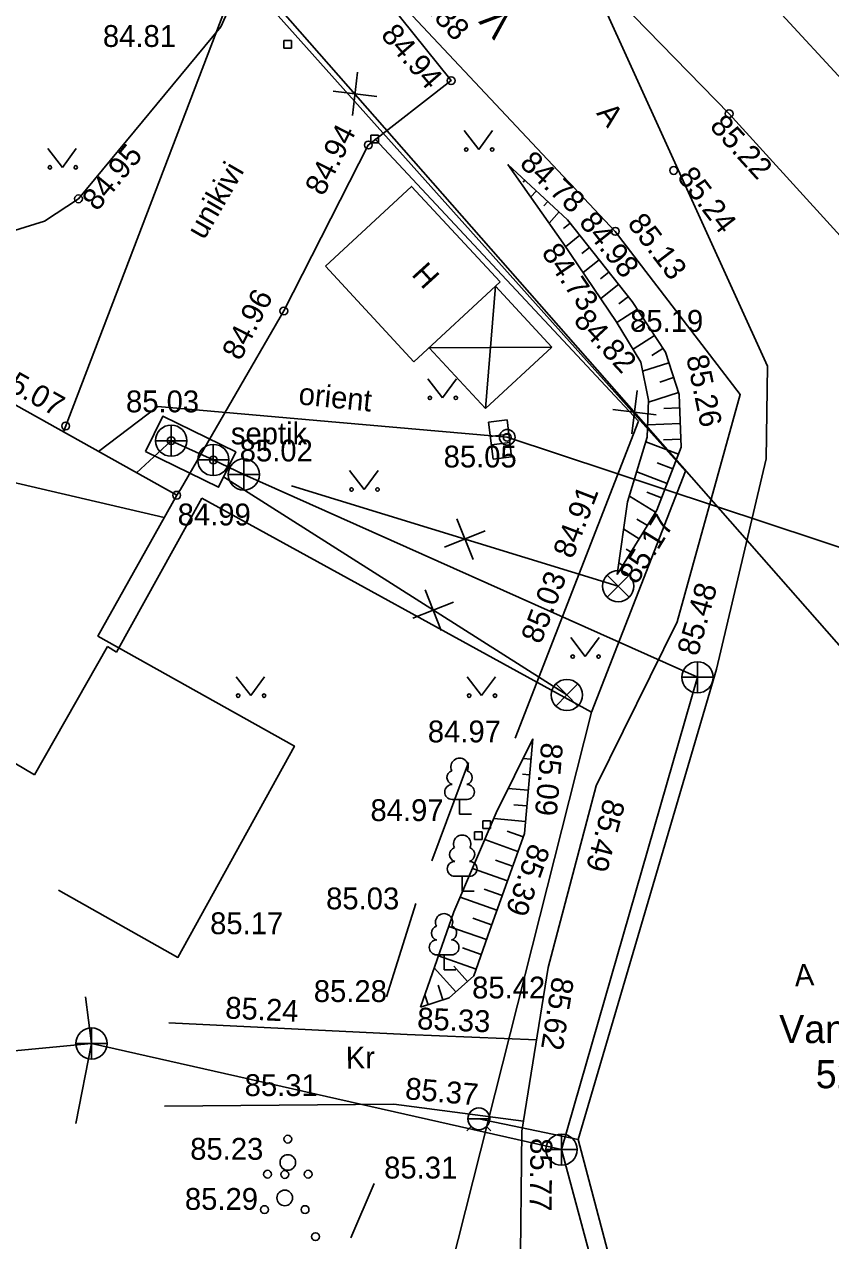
# Model space of a CAD drawing. Extents: x 648748 to 649126, y 6457789 to 6458252.
# Drawn here: x 648933.59 to 648959.42, y 6458153.11 to 6458192.08 of the extents above; entities that cross this region are included whole.
import ezdxf

# ---------------------------------------------------------------- set-up
doc = ezdxf.new("R2010")
doc.units = 0
for name, color, linetype in [('AED', 7, 'Continuous'), ('ELRAJATISMP', 7, 'Continuous'), ('HALJASTUS', 7, 'Continuous'), ('HOONE', 7, 'Continuous'), ('KKAEV', 7, 'Continuous'), ('KORGUS-EH2000', 7, 'Continuous'), ('KTRASS', 7, 'Continuous'), ('MPKAABEL', 7, 'Continuous'), ('MPOHULIIN', 7, 'Continuous'), ('PIIR', 7, 'Continuous'), ('POST', 7, 'Continuous'), ('PUU', 7, 'Continuous'), ('RAJATIS', 7, 'Continuous'), ('RAJATISEDET', 7, 'Continuous'), ('RELJEEF', 7, 'Continuous'), ('SIOHULIIN', 7, 'Continuous'), ('TEE', 7, 'Continuous'), ('TORUMP', 7, 'Continuous'), ('VKAEV', 7, 'Continuous'), ('VTRASS', 7, 'Continuous')]:
    doc.layers.add(name, color=color, linetype=linetype)

msp = doc.modelspace()

# ---------------------------------------------------------------- linework, layer by layer
at = {"layer": 'AED'}
for p, q in [((648941.902, 6458191.565), (648941.902, 6458191.315)), ((648941.902, 6458191.565), (648942.152, 6458191.565)), ((648941.902, 6458191.315), (648942.152, 6458191.315)), ((648942.152, 6458191.565), (648942.152, 6458191.315)), ((648944.692, 6458188.536), (648944.692, 6458188.286)), ((648944.692, 6458188.536), (648944.942, 6458188.536)), ((648944.692, 6458188.286), (648944.942, 6458188.286)), ((648953.264, 6458179.371), (648944.817, 6458188.411)), ((648944.942, 6458188.536), (648944.942, 6458188.286)), ((648949.319, 6458169.205), (648953.264, 6458179.371)), ((648948.279, 6458166.562), (648948.279, 6458166.312)), ((648948.279, 6458166.562), (648948.529, 6458166.562)), ((648948.529, 6458166.562), (648948.529, 6458166.312)), ((648948.01, 6458166.211), (648948.01, 6458165.961)), ((648948.01, 6458166.211), (648948.26, 6458166.211)), ((648948.01, 6458165.961), (648948.26, 6458165.961)), ((648948.26, 6458166.211), (648948.26, 6458165.961)), ((648948.279, 6458166.312), (648948.529, 6458166.312)), ((648944.05, 6458153.204), (648944.797, 6458154.938))]:
    msp.add_line(p, q, dxfattribs=at)
at = {"layer": 'ELRAJATISMP'}
for p, q in [((648949.056, 6458179.411), (648948.464, 6458179.337)), ((648948.464, 6458179.337), (648948.611, 6458178.151)), ((648949.203, 6458178.225), (648949.056, 6458179.411)), ((648949.113, 6458178.952), (648948.521, 6458178.879)), ((648949.147, 6458178.683), (648948.554, 6458178.61)), ((648948.611, 6458178.151), (648949.203, 6458178.225))]:
    msp.add_line(p, q, dxfattribs=at)
at = {"layer": 'HALJASTUS'}
for p, q in [((648947.687, 6458188.675), (648948.151, 6458188.069)), ((648948.151, 6458188.069), (648948.596, 6458188.675)), ((648934.349, 6458188.105), (648934.813, 6458187.499)), ((648934.813, 6458187.499), (648935.258, 6458188.105)), ((648946.524, 6458180.718), (648946.987, 6458180.111)), ((648946.987, 6458180.111), (648947.433, 6458180.718)), ((648944.015, 6458177.784), (648944.478, 6458177.177)), ((648944.478, 6458177.177), (648944.924, 6458177.784)), ((648951.098, 6458172.431), (648951.561, 6458171.824)), ((648951.561, 6458171.824), (648952.007, 6458172.431)), ((648940.381, 6458171.178), (648940.845, 6458170.572)), ((648940.845, 6458170.572), (648941.29, 6458171.178)), ((648947.78, 6458171.178), (648948.244, 6458170.572)), ((648948.244, 6458170.572), (648948.689, 6458171.178)), ((648947.821, 6458168.433), (648946.644, 6458165.284)), ((648946.134, 6458163.91), (648945.194, 6458160.922))]:
    msp.add_line(p, q, dxfattribs=at)
for centre in [(648947.75, 6458188.069), (648948.579, 6458188.069), (648934.412, 6458187.499), (648935.241, 6458187.499), (648946.586, 6458180.111), (648947.415, 6458180.111), (648944.077, 6458177.177), (648944.906, 6458177.177), (648951.16, 6458171.824), (648951.989, 6458171.824), (648940.444, 6458170.572), (648941.273, 6458170.572), (648947.843, 6458170.572), (648948.672, 6458170.572)]:
    msp.add_circle(centre, 0.055, dxfattribs=at)
at = {"layer": 'HOONE'}
msp.add_lwpolyline([(648931.219, 6458160.37), (648921.451, 6458165.798), (648930.234, 6458181.603), (648938.475, 6458176.993), (648935.95, 6458172.478), (648942.245, 6458168.957), (648938.513, 6458162.187), (648934.684, 6458164.338)], dxfattribs=at)
at = {"layer": 'KKAEV'}
for p, q in [((648938.299, 6458178.241), (648938.299, 6458179.241)), ((648937.799, 6458178.741), (648938.799, 6458178.741)), ((648939.648, 6458177.623), (648939.648, 6458178.623)), ((648939.148, 6458178.123), (648940.148, 6458178.123)), ((648940.622, 6458177.156), (648940.622, 6458178.156)), ((648940.122, 6458177.656), (648941.122, 6458177.656)), ((648955.157, 6458170.66), (648955.157, 6458171.66)), ((648954.657, 6458171.16), (648955.657, 6458171.16)), ((648935.747, 6458158.927), (648935.747, 6458159.927)), ((648935.247, 6458159.427), (648936.247, 6458159.427)), ((648950.799, 6458155.525), (648950.799, 6458156.525)), ((648950.299, 6458156.025), (648951.299, 6458156.025))]:
    msp.add_line(p, q, dxfattribs=at)
msp.add_lwpolyline([(648937.477, 6458178.39), (648938.029, 6458179.522), (648940.368, 6458178.382), (648939.816, 6458177.25), (648937.477, 6458178.39)], dxfattribs=at)
for centre in [(648938.299, 6458178.741), (648939.648, 6458178.123), (648940.622, 6458177.656), (648955.157, 6458171.16), (648935.747, 6458159.427), (648950.799, 6458156.025)]:
    msp.add_circle(centre, 0.5, dxfattribs=at)
at = {"layer": 'KORGUS-EH2000'}
for centre in [(648947.267, 6458190.279), (648956.171, 6458189.218), (648944.613, 6458188.214), (648954.397, 6458187.4), (648935.329, 6458186.492), (648952.525, 6458185.448), (648941.907, 6458182.899), (648934.917, 6458179.213), (648938.299, 6458178.741), (648949.064, 6458178.85), (648939.648, 6458178.123), (648938.475, 6458176.993)]:
    msp.add_circle(centre, 0.125, dxfattribs=at)
at = {"layer": 'KTRASS'}
for p, q in [((648938.299, 6458178.741), (648937.191, 6458177.711)), ((648938.299, 6458178.741), (648939.648, 6458178.123)), ((648940.622, 6458177.656), (648939.648, 6458178.123)), ((648955.157, 6458171.16), (648940.622, 6458177.656)), ((648950.975, 6458170.593), (648939.976, 6458177.578)), ((648942.155, 6458177.295), (648952.619, 6458174.082)), ((648947.45, 6458176.24), (648947.967, 6458174.939)), ((648947.058, 6458175.331), (648948.359, 6458175.848)), ((648946.434, 6458173.963), (648946.951, 6458172.662)), ((648946.042, 6458173.054), (648947.343, 6458173.572)), ((648950.799, 6458156.025), (648955.157, 6458171.16)), ((648935.747, 6458159.427), (648935.548, 6458160.919)), ((648935.747, 6458159.427), (648918.483, 6458157.779)), ((648935.747, 6458159.427), (648935.238, 6458156.861)), ((648950.799, 6458156.025), (648935.747, 6458159.427)), ((648957.262, 6458132.173), (648950.799, 6458156.025))]:
    msp.add_line(p, q, dxfattribs=at)
at = {"layer": 'MPKAABEL'}
msp.add_lwpolyline([(648935.967, 6458178.396), (648937.865, 6458179.832), (648943.331, 6458179.353), (648949.064, 6458178.85)], dxfattribs=at)
at = {"layer": 'MPOHULIIN'}
msp.add_lwpolyline([(648949.064, 6458178.85), (648980.689, 6458168.372), (648993.115, 6458162.488), (649016.276, 6458164.81), (649054.033, 6458170.656), (649094.361, 6458177.194), (649107.677, 6458175.236)], dxfattribs=at)
at = {"layer": 'PIIR'}
for p, q in [((648954.77, 6458177.77), (648938.76, 6458195.67)), ((648955.09, 6458195.42), (648987.99, 6458159.58)), ((648951.76, 6458170.04), (648954.77, 6458177.77)), ((648936.55, 6458171.97), (648939.28, 6458176.9)), ((648939.28, 6458176.9), (648951.76, 6458170.04)), ((648933.92, 6458168.04), (648936.26, 6458172.15)), ((648936.26, 6458172.15), (648936.55, 6458171.97)), ((648945.9, 6458146.87), (648951.76, 6458170.04)), ((648932.51, 6458168.86), (648933.92, 6458168.04))]:
    msp.add_line(p, q, dxfattribs=at)
at = {"layer": 'POST'}
msp.add_circle((648949.064, 6458178.85), 0.25, dxfattribs=at)
at = {"layer": 'PUU'}
for p, q in [((648947.776, 6458167.249), (648947.296, 6458167.249)), ((648947.536, 6458166.774), (648947.536, 6458167.249)), ((648947.916, 6458166.774), (648947.536, 6458166.774)), ((648947.859, 6458164.784), (648947.379, 6458164.784)), ((648947.619, 6458164.309), (648947.619, 6458164.784)), ((648947.999, 6458164.309), (648947.619, 6458164.309)), ((648947.28, 6458162.267), (648946.8, 6458162.267)), ((648947.04, 6458161.792), (648947.04, 6458162.267)), ((648947.42, 6458161.792), (648947.04, 6458161.792))]:
    msp.add_line(p, q, dxfattribs=at)
for centre, radius in [((648942.034, 6458156.363), 0.125), ((648942.034, 6458155.613), 0.25), ((648941.384, 6458155.238), 0.125), ((648941.937, 6458155.23), 0.125), ((648942.684, 6458155.238), 0.125), ((648941.937, 6458154.48), 0.25), ((648941.287, 6458154.105), 0.125), ((648942.587, 6458154.105), 0.125), ((648942.921, 6458153.239), 0.125)]:
    msp.add_circle(centre, radius, dxfattribs=at)
for centre, radius, start, end in [((648947.536, 6458168.294), 0.277, 332.58, 207.42), ((648947.366, 6458167.947), 0.233, 109.022, 253.142), ((648947.706, 6458167.947), 0.233, 286.851, 70.986), ((648947.299, 6458167.487), 0.238, 90.002, 269.395), ((648947.774, 6458167.487), 0.238, 270.605, 89.998), ((648947.619, 6458165.829), 0.277, 332.58, 207.42), ((648947.449, 6458165.482), 0.233, 109.022, 253.142), ((648947.789, 6458165.482), 0.233, 286.851, 70.986), ((648947.382, 6458165.022), 0.238, 90.002, 269.395), ((648947.857, 6458165.022), 0.238, 270.605, 89.998), ((648947.04, 6458163.312), 0.277, 332.58, 207.42), ((648946.87, 6458162.965), 0.233, 109.022, 253.142), ((648947.21, 6458162.965), 0.233, 286.851, 70.986), ((648946.803, 6458162.505), 0.238, 90.002, 269.395), ((648947.278, 6458162.505), 0.238, 270.605, 89.998)]:
    msp.add_arc(centre, radius, start, end, dxfattribs=at)
at = {"layer": 'RAJATIS'}
for p, q in [((648943.238, 6458184.328), (648946.072, 6458181.27)), ((648946.557, 6458181.718), (648948.362, 6458179.771))]:
    msp.add_line(p, q, dxfattribs=at)
for points in [[(648943.238, 6458184.328), (648946.001, 6458186.888), (648948.835, 6458183.83)], [(648948.835, 6458183.83), (648946.072, 6458181.27)], [(648948.682, 6458183.688), (648950.487, 6458181.741)], [(648950.487, 6458181.741), (648948.362, 6458179.771)]]:
    msp.add_lwpolyline(points, dxfattribs=at)
at = {"layer": 'RAJATISEDET'}
for points in [[(648948.362, 6458179.771), (648948.682, 6458183.688)], [(648950.487, 6458181.741), (648946.557, 6458181.718)]]:
    msp.add_lwpolyline(points, dxfattribs=at)
at = {"layer": 'RELJEEF'}
for p, q in [((648949.224, 6458187.385), (648949.261, 6458187.425)), ((648949.574, 6458187.026), (648949.628, 6458187.086)), ((648949.813, 6458186.548), (648949.996, 6458186.747)), ((648950.236, 6458186.269), (648950.363, 6458186.408)), ((648950.402, 6458185.712), (648950.731, 6458186.069)), ((648950.864, 6458185.542), (648951.083, 6458185.715)), ((648950.931, 6458184.957), (648951.393, 6458185.323)), ((648951.458, 6458184.737), (648951.703, 6458184.931)), ((648951.494, 6458184.128), (648952.013, 6458184.538)), ((648952.049, 6458183.93), (648952.323, 6458184.146)), ((648952.057, 6458183.299), (648952.633, 6458183.754)), ((648952.641, 6458183.123), (648952.943, 6458183.362)), ((648952.578, 6458182.527), (648953.231, 6458182.953)), ((648953.17, 6458182.316), (648953.504, 6458182.535)), ((648953.093, 6458181.669), (648953.778, 6458182.116)), ((648953.697, 6458181.466), (648954.051, 6458181.697)), ((648953.399, 6458180.966), (648954.24, 6458181.238)), ((648953.948, 6458180.618), (648954.394, 6458180.762)), ((648953.589, 6458179.976), (648954.548, 6458180.287)), ((648954.083, 6458179.771), (648954.586, 6458179.791)), ((648953.56, 6458179.251), (648954.605, 6458179.291)), ((648953.501, 6458178.708), (648954.546, 6458178.308)), ((648954.069, 6458178.77), (648954.625, 6458178.791)), ((648953.862, 6458178.034), (648954.368, 6458177.841)), ((648953.212, 6458177.748), (648954.189, 6458177.374)), ((648952.977, 6458176.966), (648953.818, 6458176.446)), ((648953.539, 6458177.087), (648954.01, 6458176.907)), ((648953.214, 6458176.232), (648953.556, 6458176.021)), ((648952.795, 6458175.903), (648953.293, 6458175.595)), ((648952.874, 6458175.267), (648953.03, 6458175.17)), ((648952.64, 6458174.823), (648952.768, 6458174.744)), ((648949.838, 6458169.035), (648949.867, 6458169.033)), ((648949.571, 6458168.557), (648949.823, 6458168.535)), ((648949.556, 6458168.056), (648949.779, 6458168.037)), ((648949.096, 6458167.595), (648949.734, 6458167.539)), ((648949.275, 6458167.078), (648949.69, 6458167.041)), ((648948.634, 6458166.633), (648949.646, 6458166.543)), ((648948.344, 6458165.959), (648949.405, 6458165.58)), ((648949.058, 6458166.235), (648949.573, 6458166.051)), ((648948.692, 6458165.304), (648949.237, 6458165.109)), ((648947.949, 6458165.039), (648949.068, 6458164.638)), ((648947.554, 6458164.118), (648948.732, 6458163.697)), ((648948.326, 6458164.373), (648948.9, 6458164.167)), ((648947.96, 6458163.442), (648948.563, 6458163.226)), ((648947.187, 6458163.175), (648948.397, 6458162.754)), ((648947.628, 6458162.492), (648948.233, 6458162.282)), ((648946.858, 6458162.231), (648948.069, 6458161.81)), ((648946.727, 6458161.853), (648947.416, 6458161.081)), ((648947.352, 6458161.904), (648947.789, 6458161.414)), ((648946.848, 6458161.293), (648947, 6458160.823)), ((648946.423, 6458160.981), (648946.525, 6458160.668))]:
    msp.add_line(p, q, dxfattribs=at)
for points in [[(648952.586, 6458174.45), (648952.92, 6458176.777), (648953.544, 6458178.851), (648953.591, 6458180.044), (648953.338, 6458181.259), (648952.556, 6458182.564), (648950.855, 6458185.068), (648949.077, 6458187.594)], [(648949.077, 6458187.594), (648950.999, 6458185.821), (648953.066, 6458183.206), (648954.131, 6458181.574), (648954.57, 6458180.217), (648954.634, 6458178.537), (648953.859, 6458176.513), (648952.586, 6458174.45)], [(648949.881, 6458169.187), (648948.713, 6458166.818), (648947.352, 6458163.649), (648946.287, 6458160.591)], [(648946.287, 6458160.591), (648947.2, 6458160.888), (648947.995, 6458161.598), (648948.503, 6458163.058), (648949.611, 6458166.156), (648949.881, 6458169.187)]]:
    msp.add_lwpolyline(points, dxfattribs=at)
at = {"layer": 'SIOHULIIN'}
msp.add_line((648896.343, 6458186.017), (648938.076, 6458176.279), dxfattribs=at)
at = {"layer": 'TEE'}
for points in [[(649107.397, 6458177.046), (649100.717, 6458173.988), (649091.348, 6458171.54), (649080.638, 6458169.649), (649068.509, 6458167.394), (649058.16, 6458165.62), (649053.786, 6458164.971), (649038.247, 6458163.046), (649010.385, 6458159.395), (648991.816, 6458157.612), (648986.6, 6458158.516), (648983.403, 6458159.789), (648978.499, 6458164.674), (648956.171, 6458189.218), (648949.185, 6458196.386), (648941.448, 6458204.958), (648937.194, 6458209.825), (648934.521, 6458215.407), (648934.235, 6458222.731), (648937.629, 6458230.732), (648939.834, 6458235.213)], [(648891.319, 6458123.494), (648901.175, 6458127.077), (648933.887, 6458139.607), (648944.575, 6458143.741), (648947.822, 6458145.717), (648948.882, 6458147.636), (648949.478, 6458151.73), (648949.531, 6458156.617), (648950.372, 6458161.859), (648951.909, 6458167.68), (648954.505, 6458172.94), (648956.528, 6458180.218), (648952.525, 6458185.448), (648945.526, 6458192.898), (648938.29, 6458202.321), (648932.248, 6458208.399), (648929.676, 6458210.569), (648928.257, 6458209.969), (648926.047, 6458207.531), (648924.786, 6458206.368), (648922.091, 6458200.973), (648909.112, 6458176.906), (648898.467, 6458156.964), (648883.402, 6458130.595)], [(648920.123, 6458168.002), (648913.413, 6458171.899), (648914.214, 6458173.602), (648920.937, 6458169.721), (648929.52, 6458184.315), (648934.24, 6458185.779), (648935.329, 6458186.492), (648939.887, 6458192.001), (648941.755, 6458196.151), (648943.221, 6458195.17), (648945.249, 6458192.789), (648947.267, 6458190.279), (648944.613, 6458188.214), (648941.907, 6458182.899), (648938.599, 6458177.177), (648938.475, 6458176.993)], [(648938.22, 6458160.091), (648945.862, 6458159.717), (648950, 6458159.539)], [(648949.583, 6458156.939), (648945.427, 6458157.48), (648938.089, 6458157.417)]]:
    msp.add_lwpolyline(points, dxfattribs=at)
at = {"layer": 'TORUMP'}
for p, q in [((648952.619, 6458174.082), (648952.264, 6458174.437)), ((648952.619, 6458174.082), (648952.974, 6458174.437)), ((648952.619, 6458174.082), (648952.264, 6458173.727)), ((648952.619, 6458174.082), (648952.974, 6458173.727)), ((648950.975, 6458170.593), (648950.62, 6458170.948)), ((648950.975, 6458170.593), (648951.33, 6458170.948)), ((648950.975, 6458170.593), (648950.62, 6458170.238)), ((648950.975, 6458170.593), (648951.33, 6458170.238))]:
    msp.add_line(p, q, dxfattribs=at)
for centre in [(648952.619, 6458174.082), (648950.975, 6458170.593)]:
    msp.add_circle(centre, 0.5, dxfattribs=at)
at = {"layer": 'VKAEV'}
for p, q in [((648947.804, 6458157.012), (648948.504, 6458157.012)), ((648947.907, 6458156.765), (648947.767, 6458156.625)), ((648948.402, 6458156.765), (648948.541, 6458156.625))]:
    msp.add_line(p, q, dxfattribs=at)
msp.add_circle((648948.154, 6458157.012), 0.35, dxfattribs=at)
at = {"layer": 'VTRASS'}
for p, q in [((648940.562, 6458193.971), (648934.844, 6458179.024)), ((648944.102, 6458189.159), (648944.271, 6458190.548)), ((648943.492, 6458189.938), (648944.881, 6458189.769)), ((648953.054, 6458178.964), (648953.224, 6458180.354)), ((648952.444, 6458179.744), (648953.834, 6458179.574)), ((648951.333, 6458156.349), (648948.154, 6458157.012))]:
    msp.add_line(p, q, dxfattribs=at)
for points in [[(648909.205, 6458232.372), (648914.854, 6458229.849), (648928.414, 6458220.256), (648945.257, 6458202.659), (648946.152, 6458201.5), (648950.981, 6458195.246), (648957.402, 6458181.131), (648957.363, 6458178.163), (648955.762, 6458171.425), (648951.333, 6458156.349), (648957.558, 6458132.798)], [(648904.231, 6458212.879), (648940.565, 6458193.977), (648965.109, 6458166.027), (648997.904, 6458167.882), (649020.691, 6458169.172)]]:
    msp.add_lwpolyline(points, dxfattribs=at)

# ---------------------------------------------------------------- texts
at = {"layer": 'KKAEV'}
msp.add_text('septik', height=0.7, dxfattribs=at).set_placement((648940.21, 6458178.625))
at = {"layer": 'KORGUS-EH2000'}
for s, rotation, p in [('84.88', 313.2145, (648945.799, 6458193.214)), ('84.94', 310.8214, (648944.983, 6458191.722)), ('85.22', 312.2935, (648955.519, 6458188.793)), ('84.94', 63.0169, (648943.172, 6458186.549)), ('84.95', 50.4002, (648935.923, 6458186.065)), ('84.78', 317.3092, (648949.427, 6458187.574)), ('85.24', 307.4247, (648954.48, 6458187.182)), ('84.98', 308.3242, (648951.335, 6458185.734)), ('85.13', 307.4247, (648952.887, 6458185.693)), ('84.73', 304.1888, (648950.138, 6458184.767)), ('84.96', 63.0169, (648940.513, 6458181.273)), ('84.82', 312.9546, (648951.155, 6458182.562)), ('85.07', 330.7793, (648932.575, 6458180.628)), ('85.26', 281.7683, (648954.794, 6458181.422)), ('84.91', 68.9968, (648951.161, 6458174.927)), ('85.17', 58.3228, (648953.208, 6458174.104)), ('85.03', 68.9968, (648950.135, 6458172.195)), ('85.48', 74.2561, (648955.163, 6458171.809)), ('85.09', 264.9096, (648950.156, 6458169.086)), ('85.49', 255.209, (648952.172, 6458167.304)), ('85.39', 250.3204, (648949.789, 6458165.876)), ('85.62', 260.8854, (648950.514, 6458161.589)), ('85.24', 357.1959, (648940.018, 6458160.231)), ('85.33', 357.5419, (648946.168, 6458159.883)), ('85.37', 354.9204, (648945.773, 6458157.645)), ('85.77', 269.3786, (648949.808, 6458156.398))]:
    msp.add_text(s, height=0.7, rotation=rotation, dxfattribs=at).set_placement(p)
for s, p in [('84.81', (648936.11, 6458191.358)), ('85.19', (648952.999, 6458182.229)), ('85.03', (648936.85, 6458179.65)), ('85.02', (648940.493, 6458178.077)), ('85.05', (648947.026, 6458177.883)), ('84.99', (648938.506, 6458176.026)), ('84.97', (648946.52, 6458169.075)), ('84.97', (648944.682, 6458166.553)), ('85.03', (648943.261, 6458163.725)), ('85.17', (648939.545, 6458162.929)), ('85.28', (648942.866, 6458160.756)), ('85.42', (648947.938, 6458160.869)), ('85.31', (648940.651, 6458157.742)), ('85.23', (648938.907, 6458155.701)), ('85.31', (648945.121, 6458155.099)), ('85.29', (648938.737, 6458154.096))]:
    msp.add_text(s, height=0.7, dxfattribs=at).set_placement(p)
at = {"layer": 'MPKAABEL'}
msp.add_text('orient', height=0.7, rotation=354.2349, dxfattribs=at).set_placement((648942.357, 6458179.908))
at = {"layer": 'PIIR'}
for s, rotation, p in [('Vanajärve tänav T1', 130.8297, (648949.329, 6458192.14)), ('Vanajärve tänav T1', 360, (648957.775, 6458159.44)), ('52801:009:0426', 360, (648958.946, 6458157.993))]:
    msp.add_text(s, height=0.9, rotation=rotation, dxfattribs=at).set_placement(p)
at = {"layer": 'RAJATIS'}
msp.add_text('H', height=0.7, rotation=312.3427, dxfattribs=at).set_placement((648945.968, 6458184.052))
at = {"layer": 'TEE'}
for s, rotation, p in [('A', 308.2934, (648951.899, 6458189.226)), ('unikivi', 59.8614, (648939.35, 6458185.15)), ('A', 3.3475, (648958.284, 6458161.254)), ('Kr', 0.3142, (648943.892, 6458158.623))]:
    msp.add_text(s, height=0.7, rotation=rotation, dxfattribs=at).set_placement(p)

doc.saveas('drawing.dxf')
